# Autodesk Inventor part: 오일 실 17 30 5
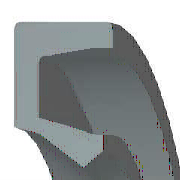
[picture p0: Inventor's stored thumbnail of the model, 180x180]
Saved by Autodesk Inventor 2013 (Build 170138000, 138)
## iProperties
IsCustomPart: 1
Created: 2012-02
Part Number: 오일 실 17 30 5
Material: 고무
Description: 오일 실 - 비스프링, 금속 케이스 GM
Document SubType Name: Modeling
Standard: JIS B 2402
Designer: mduedu
Standards Organization: JIS
Language: ko-KR
Size Designation: 17 30 5 B
Categories: <MemberInstance><Categories><Category DisplayName="샤프트 부품" InternalName="7f7aeb1f-a693-4053-b835-cee3144e0d98" Mnemonic="SHFT"><Category DisplayName="실링" Intern
Density: 0.93 g/cm^3
Author: mduedu
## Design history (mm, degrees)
body "Solid1"
revolve "회전1" stored, may be unused: angle "d27" = 360 deg
fillet "모깎기1" dims "d28" = 0.25 (= 0.05 x b)
chamfer "모따기1" distance "d29" = 0.07143 (= 0.0142857 x b); stored, may be unused: second distance "d30" = 0.25 (= 0.05 x b), angle "d35" = 45 deg
sketch "스케치2"
  geometry: L1 (-9.367, -3.238)-(-10.233, -3.863); L2 (-8.5, -1.625)-(-9.367, -3.238); L3 (-9.15, -1)-(-8.5, -1.625); L4 (-11.317, -3.75)-(-9.15, -1); L5 (-13.075, -3.75)-(-11.317, -3.75); L6 (-14.375, -1.25)-(-13.075, -3.75); L7 (-14.375, 0)-(-14.375, -1.25); L8 (-15, 0)-(-14.375, 0); L9 (-15, -5)-(-15, 0); L10 (-11.129, -5)-(-15, -5); L11 (-10.233, -3.863)-(-11.129, -5); L12 (0, -9.6)-(0, 1.6) reference; L13 (-14, 0)-(-28, 0) reference
  constraints: 22 end point, 3 horizontal, 2 vertical, 1 parallel
  dimensions: "d2" = 5 distance of L9.start L8.start (= b); "d4" = 1 vertical distance of L8.start L3.start (= 0.2 x b); "d6" = 0.625 distance of L8.start L7.start (= 0.125 x b); "d8" = 1.25 distance of L7.start L6.start (= 0.25 x b); "d10" = 1.25 vertical distance of L5.start L9.start (= 0.25 x b); "d12" = 1.3 horizontal distance of L6.start L5.start (= 0.1 x dd - 0.1 x Diam); "d14" = 1.6129 vertical distance of L2.start L1.start (= 0.322581 x b); "d16" = 0.86667 horizontal distance of L1.start L1.end (= 0.0666667 x dd - 0.0666667 x Diam); "d18" = 0.86667 horizontal distance of L2.start L1.start (= 0.0666667 x dd - 0.0666667 x Diam); "d20" = 0.625 vertical distance of L3.start L2.start (= 0.125 x b); "d22" = 0.65 horizontal distance of L3.start L2.start (= 0.05 x dd - 0.05 x Diam); "d24" = 0.625 vertical distance of L1.start L1.end (= 0.125 x b); "d26" = 2.16667 horizontal distance of L4.start L3.start (= 0.166667 x dd - 0.166667 x Diam); "d31" = 0 distance between parallel lines of L8 L13; "d32" = 15 distance between parallel lines of L12 L9 (= 0.5 x dd); "d33" = 8.5 distance from line of L12 L2.start (= 0.5 x Diam)
other parameters: "Diam" = 17 [user parameter; used in 6 equation terms], "b" = 5 [user parameter; used in 11 equation terms], "d1" = 8 (derived), "d3" = 1.6 (derived), "d5" = 1 (derived), "d7" = 2 (derived), "d9" = 2 (derived), "d11" = 2 (derived), "d13" = 2.58065 (derived), "d15" = 1.33333 (derived), "d17" = 1.33333 (derived), "d19" = 1 (derived), "d21" = 1 (derived), "d23" = 1 (derived), "d25" = 3.33333 (derived), "d34" = 0
